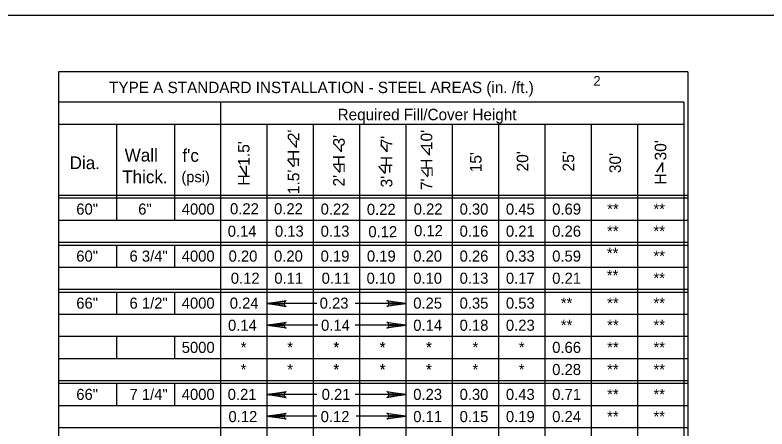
# Model space of a CAD drawing. Extents: x -22562 to -18409, y 3991 to 7171.
# Drawn here: x -19955.7 to -19768.8, y 6249.4 to 6352.4 of the extents above; entities that cross this region are included whole.
import ezdxf

# ---------------------------------------------------------------- set-up
doc = ezdxf.new("R2010")
doc.units = 0
for name, color, linetype in [('1', 7, 'Continuous'), ('2', 7, 'Continuous'), ('3', 7, 'Continuous'), ('4', 7, 'Continuous')]:
    doc.layers.add(name, color=color, linetype=linetype)

msp = doc.modelspace()

# ---------------------------------------------------------------- linework, layer by layer
at = {"layer": '1'}
for p, q in [((-19885.68, 6319.42), (-19887.25, 6321.19)), ((-19885.68, 6319.42), (-19885.68, 6321.18)), ((-19874.5, 6318.32), (-19876.07, 6320.09)), ((-19874.5, 6318.32), (-19874.5, 6320.08)), ((-19863.21, 6318.38), (-19864.78, 6320.15)), ((-19863.21, 6318.38), (-19863.21, 6320.14)), ((-19852.64, 6317.49), (-19854.2, 6319.26)), ((-19852.64, 6317.49), (-19852.64, 6319.25)), ((-19886.34, 6314.62), (-19887.9, 6316.38)), ((-19794.7, 6315.71), (-19796.26, 6313.28)), ((-19794.7, 6315.71), (-19794.7, 6313.3)), ((-19898.17, 6312.42), (-19899.73, 6314.85)), ((-19898.17, 6312.42), (-19898.17, 6314.83)), ((-19874.96, 6313.19), (-19876.52, 6314.95)), ((-19863.67, 6312.97), (-19865.23, 6314.74)), ((-19853.09, 6312.13), (-19854.65, 6313.9))]:
    msp.add_line(p, q, dxfattribs=at)
at = {"layer": '2'}
for p, q in [((-20344.85, 6352.37), (-19558.85, 6352.37)), ((-19944.85, 6338.24), (-19944.85, 6147.21)), ((-19788.45, 6338.24), (-19944.85, 6338.24)), ((-19788.45, 6338.24), (-19788.45, 6147.21)), ((-19789.45, 6330.67), (-19944.85, 6330.67)), ((-19904.57, 6330.67), (-19904.57, 6147.9)), ((-19789.45, 6330.67), (-19789.45, 6147.9)), ((-19789.45, 6325.17), (-19944.85, 6325.17)), ((-19930.46, 6325.17), (-19930.46, 6301.36)), ((-19916.07, 6325.17), (-19916.07, 6301.36)), ((-19893.05, 6325.17), (-19893.05, 6147.9)), ((-19881.54, 6325.17), (-19881.54, 6147.9)), ((-19870.03, 6325.17), (-19870.03, 6147.9)), ((-19858.52, 6325.17), (-19858.52, 6147.9)), ((-19847.01, 6325.17), (-19847.01, 6147.9)), ((-19835.5, 6325.17), (-19835.5, 6147.9)), ((-19823.99, 6325.17), (-19823.99, 6147.9)), ((-19812.48, 6325.17), (-19812.48, 6147.9)), ((-19800.96, 6325.17), (-19800.96, 6147.21)), ((-19944.85, 6307.55), (-19788.42, 6307.55)), ((-19944.85, 6306.86), (-19788.42, 6306.86)), ((-19930.46, 6306.86), (-19930.46, 6301.36)), ((-19916.07, 6306.86), (-19916.07, 6301.36)), ((-19944.85, 6301.36), (-19788.42, 6301.36)), ((-19944.85, 6295.85), (-19788.42, 6295.85)), ((-19944.85, 6295.16), (-19788.42, 6295.16)), ((-19930.46, 6295.16), (-19930.46, 6289.66)), ((-19916.07, 6295.16), (-19916.07, 6289.66)), ((-19944.85, 6289.66), (-19788.42, 6289.66)), ((-19944.85, 6284.15), (-19788.42, 6284.15)), ((-19944.85, 6283.46), (-19944.85, 6283.46)), ((-19944.85, 6283.46), (-19788.42, 6283.46)), ((-19930.46, 6283.46), (-19930.46, 6277.96)), ((-19916.07, 6283.46), (-19916.07, 6277.96)), ((-19880.66, 6280.59), (-19893.05, 6280.59)), ((-19858.52, 6280.59), (-19871.1, 6280.59)), ((-19944.85, 6277.96), (-19788.42, 6277.96)), ((-19880.43, 6275.22), (-19893.05, 6275.22)), ((-19858.52, 6275.22), (-19871.1, 6275.22)), ((-19944.85, 6272.45), (-19788.42, 6272.45)), ((-19930.46, 6272.45), (-19930.46, 6266.95)), ((-19916.07, 6272.45), (-19916.07, 6266.95)), ((-19944.85, 6266.95), (-19788.42, 6266.95)), ((-19944.85, 6261.45), (-19788.42, 6261.45)), ((-19944.85, 6260.76), (-19788.42, 6260.76)), ((-19930.46, 6260.76), (-19930.46, 6255.25)), ((-19916.07, 6260.76), (-19916.07, 6255.25)), ((-19880.66, 6257.95), (-19893.05, 6257.95)), ((-19858.52, 6257.95), (-19871.1, 6257.95)), ((-19944.85, 6255.25), (-19788.42, 6255.25)), ((-19880.66, 6252.58), (-19893.05, 6252.58)), ((-19858.52, 6252.58), (-19870.87, 6252.58)), ((-19944.85, 6249.75), (-19788.42, 6249.75))]:
    msp.add_line(p, q, dxfattribs=at)
for points in [[(-19888.53, 6280.02), (-19888.7, 6280.35), (-19893.05, 6280.59), (-19888.53, 6280.02), (-19888.3, 6279.82), (-19893.05, 6280.59), (-19888.7, 6280.81), (-19888.54, 6281.13), (-19893.05, 6280.59), (-19888.3, 6281.35), (-19888.54, 6281.13)], [(-19863.04, 6281.16), (-19862.88, 6280.83), (-19858.52, 6280.59), (-19863.04, 6281.16), (-19863.28, 6281.36), (-19858.52, 6280.59), (-19862.87, 6280.37), (-19863.03, 6280.05), (-19858.52, 6280.59), (-19863.28, 6279.83), (-19863.03, 6280.05)], [(-19888.53, 6274.65), (-19888.7, 6274.98), (-19893.05, 6275.22), (-19888.53, 6274.65), (-19888.3, 6274.45), (-19893.05, 6275.22), (-19888.7, 6275.44), (-19888.54, 6275.76), (-19893.05, 6275.22), (-19888.3, 6275.98), (-19888.54, 6275.76)], [(-19863.04, 6275.79), (-19862.88, 6275.46), (-19858.52, 6275.22), (-19863.04, 6275.79), (-19863.28, 6275.99), (-19858.52, 6275.22), (-19862.87, 6275.01), (-19863.03, 6274.68), (-19858.52, 6275.22), (-19863.28, 6274.46), (-19863.03, 6274.68)], [(-19888.53, 6257.38), (-19888.7, 6257.71), (-19893.05, 6257.95), (-19888.53, 6257.38), (-19888.3, 6257.18), (-19893.05, 6257.95), (-19888.7, 6258.17), (-19888.54, 6258.49), (-19893.05, 6257.95), (-19888.3, 6258.71), (-19888.54, 6258.49)], [(-19863.04, 6258.52), (-19862.88, 6258.19), (-19858.52, 6257.95), (-19863.04, 6258.52), (-19863.28, 6258.72), (-19858.52, 6257.95), (-19862.87, 6257.73), (-19863.03, 6257.41), (-19858.52, 6257.95), (-19863.28, 6257.19), (-19863.03, 6257.41)], [(-19888.53, 6252.01), (-19888.7, 6252.34), (-19893.05, 6252.58), (-19888.53, 6252.01), (-19888.3, 6251.82), (-19893.05, 6252.58), (-19888.7, 6252.8), (-19888.54, 6253.12), (-19893.05, 6252.58), (-19888.3, 6253.34), (-19888.54, 6253.12)], [(-19863.04, 6253.15), (-19862.88, 6252.82), (-19858.52, 6252.58), (-19863.04, 6253.15), (-19863.28, 6253.35), (-19858.52, 6252.58), (-19862.87, 6252.37), (-19863.03, 6252.04), (-19858.52, 6252.58), (-19863.28, 6251.83), (-19863.03, 6252.04)]]:
    msp.add_lwpolyline(points, dxfattribs=at)

# ---------------------------------------------------------------- texts
at = {"layer": '1'}
for s, height, p in [("f'c", 3.172, (-19914.07, 6315.85)), ('Thick.', 3.172, (-19929.04, 6310.53)), ('(psi)', 2.719, (-19914.31, 6310.77)), ('60"', 2.751, (-19940.44, 6302.73)), ('60"', 2.751, (-19940.44, 6291.03)), ('66"', 2.751, (-19940.44, 6279.33)), ('66"', 2.751, (-19940.44, 6256.63))]:
    msp.add_text(s, height=height, dxfattribs=at).set_placement(p)
for s, height, p in [("15'", 2.883, (-19839.72, 6313.25)), ("20'", 2.883, (-19828.1, 6313.46)), ("25'", 2.883, (-19816.68, 6313.46)), ("30'", 2.883, (-19805.06, 6313.04)), ('=', 2.88, (-19884.39, 6314.59)), ('=', 2.88, (-19873.01, 6313.16)), ('=', 2.88, (-19861.72, 6312.94)), ('=', 2.88, (-19851.14, 6312.1))]:
    msp.add_text(s, height=height, rotation=90, dxfattribs=at).set_placement(p)
at = {"layer": '2'}
for s, height, p in [('TYPE A STANDARD INSTALLATION - STEEL AREAS (in. /ft.)', 2.8357, (-19932.29, 6332.95)), ('2', 2.42, (-19811.92, 6334.78)), ('Required Fill/Cover Height', 2.8357, (-19875.48, 6326.2))]:
    msp.add_text(s, height=height, dxfattribs=at).set_placement(p)
at = {"layer": '3'}
for s, height, p in [('0.22', 2.753, (-19902.23, 6302.8)), ('0.22', 2.753, (-19891.28, 6302.8)), ('0.22', 2.753, (-19879.71, 6302.73)), ('0.22', 2.753, (-19868.22, 6302.66)), ('0.22', 2.753, (-19856.57, 6302.73)), ('0.30', 2.753, (-19845.17, 6302.73)), ('0.45', 2.753, (-19833.66, 6302.73)), ('0.69', 2.753, (-19822.15, 6302.73)), ('**', 2.753, (-19808.5, 6302.73)), ('**', 2.753, (-19796.99, 6302.73)), ('0.16', 2.753, (-19845.17, 6297.23)), ('0.21', 2.753, (-19833.66, 6297.23)), ('0.26', 2.753, (-19822.15, 6297.23)), ('**', 2.753, (-19808.5, 6297.23)), ('**', 2.753, (-19796.99, 6297.23)), ('0.20', 2.753, (-19902.59, 6291.03)), ('0.20', 2.753, (-19891.3, 6291.03)), ('0.19', 2.753, (-19879.72, 6291.03)), ('0.19', 2.753, (-19868.21, 6291.03)), ('0.20', 2.753, (-19856.69, 6291.03)), ('0.26', 2.753, (-19845.17, 6291.03)), ('0.33', 2.753, (-19833.66, 6291.03)), ('0.59', 2.753, (-19822.15, 6291.03)), ('**', 2.753, (-19808.57, 6291.72)), ('**', 2.753, (-19796.99, 6291.03)), ('0.12', 2.752, (-19902.04, 6285.53)), ('0.11', 2.753, (-19891.22, 6285.53)), ('0.11', 2.751, (-19879.46, 6285.53)), ('0.10', 2.751, (-19868.29, 6285.53)), ('0.10', 2.751, (-19856.69, 6285.53)), ('0.13', 2.753, (-19845.17, 6285.53)), ('0.17', 2.753, (-19833.66, 6285.53)), ('0.21', 2.753, (-19822.15, 6285.53)), ('**', 2.753, (-19808.57, 6286.22)), ('**', 2.753, (-19796.99, 6285.53)), ('0.24', 2.753, (-19902.3, 6279.33)), ('0.23', 2.753, (-19879.95, 6279.33)), ('0.25', 2.753, (-19856.69, 6279.33)), ('0.35', 2.753, (-19845.17, 6279.33)), ('0.53', 2.753, (-19833.66, 6279.33)), ('**', 2.753, (-19820.01, 6279.33)), ('**', 2.753, (-19808.5, 6279.33)), ('**', 2.753, (-19796.99, 6279.33)), ('0.14', 2.753, (-19902.73, 6273.83)), ('0.14', 2.753, (-19879.6, 6273.83)), ('0.14', 2.753, (-19856.69, 6273.83)), ('0.18', 2.753, (-19845.17, 6273.83)), ('0.23', 2.753, (-19833.66, 6273.83)), ('**', 2.753, (-19820.01, 6273.83)), ('**', 2.753, (-19808.5, 6273.83)), ('**', 2.753, (-19796.99, 6273.83)), ('*', 2.75, (-19899.58, 6268.32)), ('*', 2.75, (-19888.01, 6268.32)), ('*', 2.75, (-19876.56, 6268.32)), ('*', 2.75, (-19876.5, 6268.32)), ('*', 2.75, (-19865.05, 6268.32)), ('*', 2.75, (-19864.99, 6268.32)), ('*', 2.75, (-19853.54, 6268.32)), ('*', 2.75, (-19853.48, 6268.32)), ('*', 2.75, (-19841.96, 6268.32)), ('*', 2.75, (-19830.45, 6268.32)), ('0.66', 2.753, (-19822.15, 6268.32)), ('**', 2.753, (-19808.5, 6268.32)), ('**', 2.753, (-19796.99, 6268.32)), ('*', 2.75, (-19899.58, 6262.82)), ('*', 2.75, (-19888.01, 6262.82)), ('*', 2.75, (-19876.56, 6262.82)), ('*', 2.75, (-19876.5, 6262.82)), ('*', 2.75, (-19865.05, 6262.82)), ('*', 2.75, (-19864.99, 6262.82)), ('*', 2.75, (-19853.54, 6262.82)), ('*', 2.75, (-19853.48, 6262.82)), ('*', 2.75, (-19841.96, 6262.82)), ('*', 2.75, (-19830.45, 6262.82)), ('0.28', 2.753, (-19822.15, 6262.82)), ('**', 2.753, (-19808.5, 6262.82)), ('**', 2.753, (-19796.99, 6262.82)), ('0.21', 2.753, (-19902.81, 6256.63)), ('0.21', 2.753, (-19879.45, 6256.63)), ('0.23', 2.753, (-19856.69, 6256.63)), ('0.30', 2.753, (-19845.17, 6256.63)), ('0.43', 2.753, (-19833.66, 6256.63)), ('0.71', 2.753, (-19822.15, 6256.63)), ('**', 2.753, (-19808.5, 6256.63)), ('**', 2.753, (-19796.99, 6256.63)), ('0.11', 2.753, (-19856.69, 6251.12)), ('0.15', 2.753, (-19845.17, 6251.12)), ('0.19', 2.753, (-19833.66, 6251.12)), ('0.24', 2.753, (-19822.15, 6251.12)), ('**', 2.753, (-19808.5, 6251.12)), ('**', 2.753, (-19796.99, 6251.12))]:
    msp.add_text(s, height=height, dxfattribs=at).set_placement(p)
for s, p in [('0.14', (-19902.8, 6297.22)), ('0.13', (-19891.07, 6297.22)), ('0.13', (-19879.7, 6297.22)), ('0.12', (-19867.84, 6297.1)), ('0.12', (-19856.48, 6297.35)), ('0.12', (-19902.61, 6251.11)), ('0.12', (-19879.7, 6251.11))]:
    msp.add_text(s, height=2.751, rotation=0.1244, dxfattribs=at).set_placement(p)
at = {"layer": '4'}
for s, height, p in [("1.5'  H  2'", 2.8834, (-19885, 6307.81)), ("7'  H  10'", 2.883, (-19851.95, 6308.82)), ("2'  H  3'", 2.883, (-19873.72, 6309.71)), ("3'  H  7'", 2.883, (-19861.88, 6309.49)), ("H   30'", 2.883, (-19793.78, 6310.2)), ("H  1.5'", 2.883, (-19897.38, 6309.95))]:
    msp.add_text(s, height=height, rotation=90, dxfattribs=at).set_placement(p)
for s, height, p in [('Wall', 3.172, (-19928.42, 6315.93)), ('Dia.', 3.172, (-19942.1, 6314.03)), ('6"', 2.753, (-19925.05, 6302.73)), ('4000', 2.753, (-19914.24, 6302.73)), ('6 3/4"', 2.751, (-19927.21, 6291.03)), ('4000', 2.753, (-19914.24, 6291.03)), ('6 1/2"', 2.751, (-19927.21, 6279.33)), ('4000', 2.753, (-19914.24, 6279.33)), ('5000', 2.753, (-19914.24, 6268.32)), ('7 1/4"', 2.751, (-19927.21, 6256.63)), ('4000', 2.753, (-19914.24, 6256.63))]:
    msp.add_text(s, height=height, dxfattribs=at).set_placement(p)

doc.saveas('drawing.dxf')
